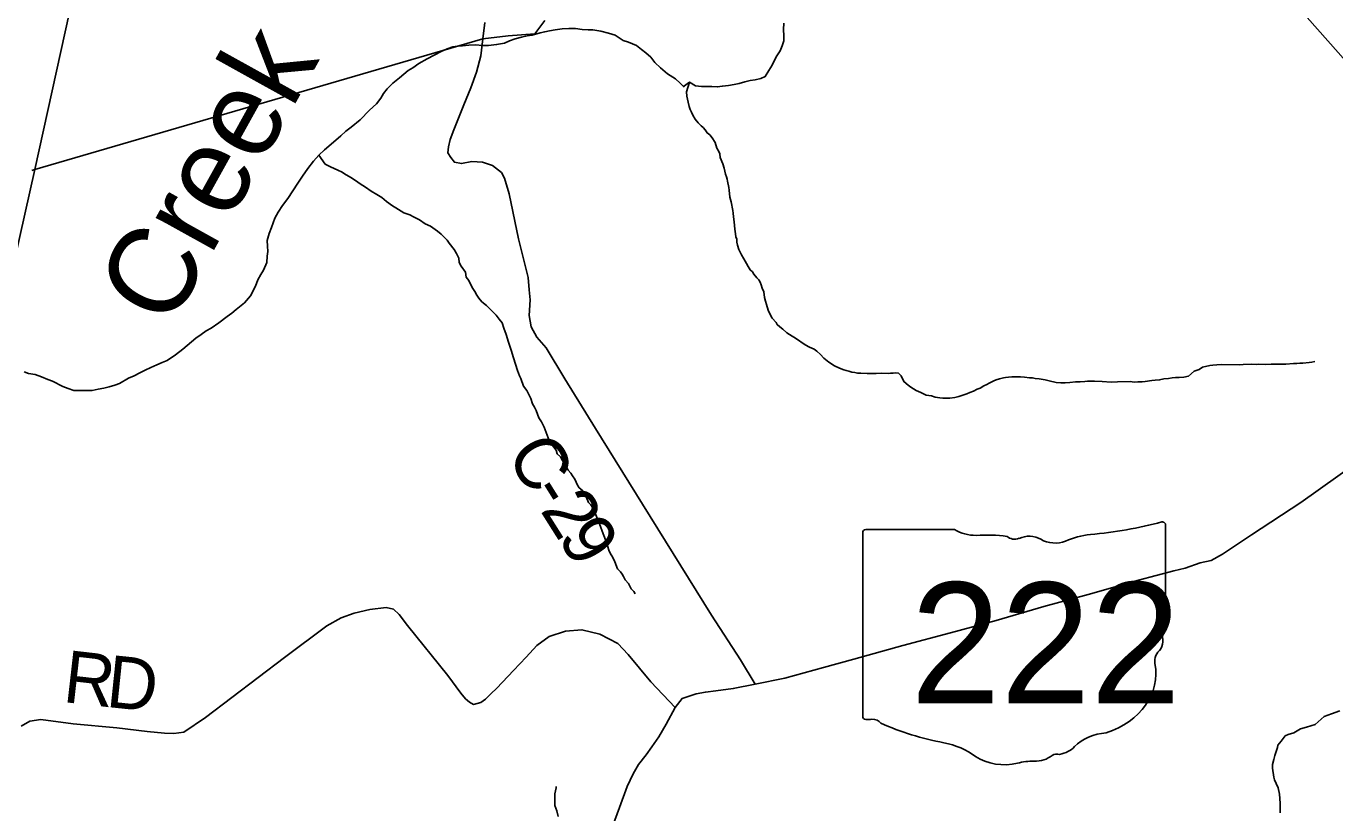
# Model space of a CAD drawing. Extents: x 1310247 to 1664935, y 235267 to 584339.
# Drawn here: x 1499619 to 1507145, y 298459 to 302982 of the extents above; entities that cross this region are included whole.
import ezdxf

# ---------------------------------------------------------------- set-up
doc = ezdxf.new("R2010")
doc.units = 0
for name, color, linetype in [('GM_X_County_Road', 7, 'Continuous'), ('GM_X_County_Road_Text', 7, 'Continuous'), ('GM_X_Minor_River', 7, 'Continuous'), ('GM_X_Minor_River_Text', 7, 'Continuous'), ('GM_X_State_Location', 7, 'Continuous'), ('GM_X_State_Route', 7, 'Continuous'), ('GM_X_State_Shield', 7, 'Continuous'), ('GM_X_Township', 7, 'Continuous'), ('GM_X_Township_Road', 7, 'Continuous'), ('GM_X_Township_Road_Text', 7, 'Continuous'), ('GM_X_Township_ROW', 7, 'Continuous')]:
    doc.layers.add(name, color=color, linetype=linetype)

msp = doc.modelspace()

# ---------------------------------------------------------------- linework, layer by layer
at = {"layer": 'GM_X_County_Road'}
msp.add_lwpolyline([(1503810.8, 299198.2), (1503727.6, 299337.9), (1503560.6, 299594.9), (1503162.8, 300234.4), (1502892.6, 300669.5), (1502716.7, 300955.1), (1502609.1, 301133.2), (1502556.3, 301194.7), (1502523.4, 301254), (1502512.4, 301317.7), (1502516.8, 301407.8), (1502512.4, 301467.1), (1502505.8, 301537.5), (1502450.9, 301759.4), (1502395.9, 302018.7), (1502369.6, 302108.8), (1502352, 302141.8), (1502300.1, 302180.6), (1502243.8, 302199.4), (1502181.8, 302203.7), (1502122.7, 302192.1), (1502082.2, 302199.4), (1502060.6, 302226.8), (1502044.7, 302254.2), (1502047.6, 302288.8), (1502057.7, 302330.7), (1502079.3, 302387), (1502135.6, 302529.8), (1502176, 302627.9), (1502209.2, 302718.8), (1502233.7, 302812.6), (1502245.3, 302909.3), (1502256.9, 303003.1)], dxfattribs=at)
at = {"layer": 'GM_X_Minor_River'}
for points in [[(1503399.3, 302636.4), (1503433.3, 302659.7), (1503469.1, 302639), (1503503.1, 302636.4), (1503561.3, 302635.3), (1503593.4, 302632.7), (1503623.5, 302638.2), (1503657.7, 302641.5), (1503689.9, 302646.9), (1503720.1, 302652.4), (1503752.4, 302661.8), (1503782.6, 302669.3), (1503810.8, 302674.7), (1503843.1, 302682.2), (1503869.4, 302693.7), (1503890.1, 302727.4), (1503908.7, 302759.1), (1503931.7, 302806.7), (1503954.4, 302840.4), (1503967, 302870.2), (1503975.5, 302898.1), (1503976, 302926.1), (1503974.8, 302964.2), (1503975.4, 303000.3)], [(1499893.5, 300887.5), (1499999.4, 300888.1), (1500033.5, 300895.6), (1500065.6, 300901.2), (1500095.7, 300908.8), (1500129.8, 300918.3), (1500155.9, 300928), (1500208.3, 300957.3), (1500240.5, 300970.9), (1500272.8, 300988.5), (1500303, 301004.1), (1500335.2, 301019.6), (1500371.4, 301035.2), (1500401.6, 301048.8), (1500429.7, 301060.4), (1500478.1, 301091.8), (1500520.6, 301125.2), (1500569.1, 301166.6), (1500595.4, 301188.3), (1500625.7, 301209.9), (1500654, 301229.5), (1500682.2, 301245.1), (1500726.6, 301276.6), (1500775.1, 301311.9), (1500801.4, 301331.6), (1500827.7, 301353.2), (1500874.2, 301390.6), (1500908.8, 301432.2), (1500937.5, 301487.8), (1500952, 301523.7), (1500968.4, 301553.5), (1500984.8, 301579.3), (1501003.4, 301623), (1501005.9, 301659), (1501008.3, 301687), (1501006.7, 301717), (1501005.2, 301749.1), (1501015.8, 301791), (1501030.2, 301824.8), (1501049, 301878.6), (1501067.4, 301912.3), (1501094, 301952), (1501124.5, 301991.6), (1501181.7, 302078.9), (1501208.3, 302120.6), (1501238.9, 302164.2), (1501271.5, 302205.8), (1501302, 302241.4), (1501334.4, 302271), (1501399.1, 302326.1), (1501429.5, 302351.8), (1501457.8, 302379.4), (1501488.1, 302401), (1501540.7, 302444.3), (1501593.5, 302499.7), (1501634, 302535.1), (1501658.4, 302568.8), (1501674.8, 302594.6), (1501695.2, 302622.4), (1501727.6, 302654), (1501766, 302685.5), (1501816.6, 302726.8), (1501842.8, 302742.5), (1501877.1, 302768.1), (1501925.5, 302795.5), (1501965.8, 302814.9), (1502006, 302836.4), (1502040.2, 302852), (1502072.4, 302863.5), (1502098.4, 302867.2), (1502128.5, 302868.8), (1502164.5, 302872.3), (1502202.5, 302875.8), (1502242.5, 302871.3), (1502278.4, 302870.8), (1502324.5, 302876.2), (1502370.6, 302885.6), (1502398.8, 302897.2), (1502430.9, 302908.8), (1502467, 302918.3), (1502501.1, 302925.9), (1502529.2, 302931.5), (1502575.4, 302944.9), (1502601.4, 302950.5), (1502629.5, 302956.2), (1502661.6, 302961.8), (1502701.6, 302967.2), (1502739.6, 302968.7), (1502777.6, 302968.2), (1502817.5, 302963.7), (1502851.5, 302961.2), (1502877.5, 302960.9), (1502923.4, 302954.3), (1502967.2, 302941.7), (1503007, 302931.1), (1503052.6, 302900.5), (1503082.4, 302890.1), (1503128.1, 302871.5), (1503157.8, 302849.1), (1503183.5, 302828.7), (1503211.2, 302804.3)], [(1503211.2, 302804.3), (1503234.7, 302774), (1503266.3, 302743.5), (1503307.8, 302709), (1503353.4, 302680.3), (1503381, 302654), (1503404, 302631.9)], [(1503433.3, 302659.7), (1503416.1, 302605.1), (1503417.8, 302579), (1503425.4, 302544.7), (1503431.1, 302520.6), (1503436.9, 302502.5), (1503444.8, 302488.3), (1503452.6, 302470.1), (1503466.4, 302447.9), (1503484.2, 302425.6), (1503500.1, 302409.4), (1503512, 302399.2), (1503523.9, 302387), (1503535.7, 302368.8), (1503551.7, 302356.6), (1503563.5, 302340.4), (1503581.3, 302314.1), (1503590.9, 302281.8), (1503600.8, 302265.7), (1503608.6, 302247.5), (1503610.3, 302227.4), (1503626, 302191.1), (1503633.7, 302164.9), (1503641.3, 302130.7), (1503647.2, 302116.6), (1503651, 302102.5), (1503652.9, 302090.5), (1503660.5, 302054.2), (1503662.3, 302040.2), (1503665.8, 302000), (1503673.5, 301971.8), (1503683, 301921.5), (1503684.8, 301907.5), (1503686.6, 301885.4), (1503690.2, 301857.3), (1503693.7, 301815.1), (1503697.4, 301789), (1503701.2, 301770.8), (1503705.1, 301756.8), (1503706.9, 301740.7), (1503710.7, 301722.6), (1503718.4, 301698.4), (1503732.1, 301668.1), (1503745.9, 301643.9), (1503753.8, 301631.8), (1503761.6, 301617.6), (1503771.5, 301599.5), (1503783.3, 301581.2), (1503795.2, 301569.1), (1503803.1, 301556.9), (1503820.9, 301534.6), (1503832.8, 301524.5), (1503840.7, 301510.3), (1503846.5, 301494.2), (1503852.3, 301476.1), (1503862.1, 301453.9), (1503865.7, 301421.8), (1503871.5, 301401.6), (1503877.3, 301381.5), (1503886.9, 301349.3), (1503892.8, 301335.1), (1503908.5, 301302.9), (1503932.3, 301278.5), (1503938.1, 301266.4), (1503954.1, 301254.1), (1503969.9, 301239.9), (1503993.8, 301219.5), (1504023.7, 301199.1), (1504043.6, 301188.8), (1504099.4, 301150), (1504123.3, 301135.7), (1504151.3, 301125.3), (1504165.2, 301113.1), (1504187.1, 301094.8), (1504206.9, 301072.5), (1504234.7, 301050.1), (1504268.6, 301029.6), (1504296.6, 301015.2), (1504320.6, 301006.9), (1504334.6, 301002.7), (1504350.6, 300998.5), (1504366.6, 300992.3), (1504384.6, 300990), (1504400.7, 300987.8), (1504418.7, 300987.6), (1504454.9, 300985.1), (1504493, 300984.7), (1504507.1, 300984.5), (1504537.2, 300986.1), (1504575.4, 300985.7), (1504589.4, 300987.5), (1504605.5, 300987.3), (1504619.6, 300989.1), (1504635.6, 300986.9), (1504651.5, 300970.7), (1504667.2, 300938.4), (1504691, 300918), (1504706.9, 300905.8), (1504736.8, 300887.4), (1504764.8, 300875), (1504794.7, 300860.6)], [(1501302, 302241.4), (1501338.6, 302189.4), (1501368.5, 302173), (1501410.5, 302154.4), (1501436.4, 302142), (1501450.4, 302133.8), (1501486.3, 302111.3), (1501512.2, 302094.9), (1501540.1, 302076.5), (1501569.9, 302056.1), (1501603.8, 302033.6), (1501635.7, 302015.1), (1501663.6, 301996.7), (1501691.5, 301974.3), (1501725.3, 301949.8), (1501745.2, 301937.5), (1501791.1, 301908.9), (1501825.1, 301898.4), (1501847, 301886.1), (1501881, 301869.6), (1501912.8, 301845.2), (1501944.8, 301832.7), (1501984.6, 301804.2), (1502006.5, 301785.8), (1502040.2, 301751.3), (1502052.1, 301735.1), (1502079.7, 301698.7), (1502093.5, 301674.4), (1502107.2, 301648.2), (1502109, 301624.1), (1502120.7, 301601.8), (1502146.4, 301567.4), (1502150.1, 301539.3), (1502163.9, 301519.1), (1502183.5, 301478.7), (1502199.3, 301456.4), (1502211.1, 301436.2), (1502222.9, 301418), (1502238.8, 301397.8), (1502266.6, 301375.3), (1502294.4, 301346.9), (1502322.2, 301320.5), (1502340, 301298.2), (1502355.8, 301275.9), (1502365.5, 301245.7), (1502379.1, 301209.4), (1502392.6, 301165.1), (1502408.1, 301118.8), (1502421.6, 301074.5), (1502444.8, 301002), (1502456.5, 300971.8), (1502464.4, 300955.6), (1502479.9, 300911.3), (1502497.7, 300887), (1502509.5, 300864.8), (1502521.2, 300840.6), (1502530.9, 300810.4), (1502542.7, 300792.2), (1502552.5, 300772), (1502568.1, 300729.7), (1502581.8, 300707.4), (1502597.6, 300677.1), (1502620.9, 300614.7), (1502632.6, 300588.4), (1502666.2, 300543.9), (1502672, 300523.8), (1502691.9, 300505.5), (1502703.7, 300485.2), (1502719.5, 300463), (1502735.1, 300428.7), (1502751, 300412.5), (1502760.8, 300396.3), (1502774.7, 300378.1), (1502790.3, 300343.8), (1502800.2, 300327.6), (1502816.1, 300313.4), (1502825.9, 300297.2), (1502839.7, 300275), (1502853.4, 300242.7), (1502867.3, 300230.5), (1502875.1, 300214.3), (1502886.9, 300196.1), (1502894.7, 300172), (1502902.5, 300153.8), (1502922, 300105.4), (1502931.7, 300079.2), (1502941.4, 300053), (1502951.2, 300028.8), (1502958.9, 300006.7), (1502970.5, 299968.4), (1502980.3, 299948.2), (1502990.2, 299930.1), (1503003.9, 299901.8), (1503019.4, 299861.5), (1503037.3, 299845.2), (1503047.2, 299831.1), (1503055, 299816.9), (1503062.9, 299798.8), (1503082.7, 299776.5), (1503098.4, 299746.2), (1503114.3, 299732)], [(1504794.7, 300860.6), (1504824.8, 300856.2), (1504846.8, 300849.9), (1504872.9, 300845.6), (1504890.9, 300843.4), (1504931.1, 300842.9), (1504959.3, 300846.5), (1504983.4, 300852.2), (1505027.8, 300867.7), (1505046, 300875.5), (1505066.1, 300883.3), (1505088.4, 300895.1), (1505104.5, 300900.9), (1505126.8, 300914.7), (1505142.9, 300922.5), (1505157.1, 300930.3), (1505183.3, 300942), (1505197.5, 300947.9), (1505215.6, 300953.7), (1505239.8, 300959.4), (1505251.8, 300961.2), (1505267.9, 300963.1), (1505288, 300966.8), (1505338.2, 300966.2), (1505360.3, 300963.9), (1505388.4, 300959.6), (1505406.4, 300959.3), (1505422.5, 300957.1), (1505444.5, 300954.9), (1505478.6, 300948.4), (1505502.6, 300942.1), (1505542.7, 300933.6), (1505568.8, 300931.3), (1505594.9, 300930.9), (1505621, 300932.6), (1505653.2, 300936.2), (1505681.3, 300937.9), (1505707.4, 300939.6), (1505723.5, 300941.4), (1505763.7, 300940.9), (1505807.8, 300938.3), (1505858, 300935.7), (1505894.2, 300937.3), (1505968.5, 300938.3), (1505990.5, 300936.1), (1506012.7, 300937.8), (1506036.8, 300937.5), (1506054.8, 300939.3), (1506093.1, 300944.8), (1506111.2, 300946.6), (1506137.3, 300948.3), (1506161.5, 300954), (1506187.6, 300955.7), (1506209.7, 300959.4), (1506227.8, 300961.2), (1506249.9, 300963), (1506276.1, 300964.6), (1506304.2, 300970.3), (1506336.7, 300998), (1506364.9, 301007.7), (1506383.2, 301021.5), (1506425.5, 301031), (1506443.6, 301032.8), (1506465.7, 301034.5), (1506495.8, 301036.1), (1506596.2, 301034.9), (1506618.3, 301036.6), (1506664.5, 301038.1), (1506692.6, 301037.7), (1506706.7, 301039.6), (1506744.8, 301037.1), (1506779, 301038.7), (1506827.2, 301038.1), (1506863.4, 301039.6), (1506907.6, 301043.1), (1506925.7, 301042.9), (1506943.8, 301044.6), (1506961.8, 301044.4), (1506998, 301048), (1507012.1, 301049.8), (1507030.2, 301053.6)], [(1499607.1, 300995.3), (1499632.9, 300985), (1499670.8, 300978.5), (1499706.6, 300966), (1499744.4, 300951.5), (1499770.3, 300941.1), (1499829.8, 300910.3), (1499861.6, 300897.9), (1499893.5, 300887.5)], [(1503114.3, 299732), (1503122.1, 299717.8)], [(1506830.1, 298458.3), (1506830.8, 298514.5), (1506827.4, 298566.7), (1506819.8, 298602.9), (1506808.1, 298627.1), (1506798.3, 298649.3), (1506794.4, 298663.4), (1506787, 298715.6), (1506787.3, 298735.7), (1506793.7, 298765.7), (1506800, 298787.7), (1506814.6, 298833.7), (1506816.8, 298847.7), (1506837.1, 298871.5), (1506859.6, 298901.3), (1506875.7, 298909.1), (1506910, 298918.8), (1506948.4, 298942.3), (1506982.7, 298952), (1507031.1, 298967.4), (1507083.8, 299012.9), (1507126.2, 299028.4), (1507174.6, 299045.9)], [(1502678, 298437.4), (1502670.5, 298469.6), (1502659, 298501.7), (1502659.9, 298567.8), (1502666.4, 298601.7), (1502666.5, 298609.7)]]:
    msp.add_lwpolyline(points, dxfattribs=at)
at = {"layer": 'GM_X_State_Route'}
msp.add_lwpolyline([(1502978.3, 298344.5), (1503030.7, 298490.2), (1503075.4, 298610.8), (1503109.6, 298683.6), (1503139.9, 298736), (1503183.9, 298792.8), (1503217.3, 298837.6), (1503256.7, 298894.9), (1503299.2, 298968.4), (1503351.3, 299064.5), (1503391, 299115.7), (1503471.8, 299143.1), (1503525.2, 299153.2), (1503585.8, 299160.5), (1503685.4, 299173.5), (1503810.8, 299198.2), (1503981.7, 299232.1), (1504203.7, 299294.7), (1504378.8, 299341.6), (1504661.4, 299420.2), (1504934.4, 299494.6), (1505197.7, 299565), (1505472.1, 299644.9), (1505727.1, 299713.8), (1506015.5, 299796.5), (1506218.8, 299851.1), (1506284.1, 299865.5), (1506370.6, 299895.7), (1506434.1, 299909.2), (1506499.3, 299945.7), (1506562.6, 299988.3), (1506664.8, 300058), (1506948.8, 300243.5), (1507275.4, 300474.9)], dxfattribs=at)
at = {"layer": 'GM_X_State_Shield'}
for p, q in [((1504431, 300069.6), (1504431, 299013)), ((1504957.8, 300087.8), (1504448.2, 300087.8)), ((1506171.2, 299561.3), (1506171.2, 300114)), ((1506171.1, 299561.4), (1506171.2, 299561.3))]:
    msp.add_line(p, q, dxfattribs=at)
for centre, major_axis, start_param, end_param in [((1505551.4, 301528.4), (1845.5, 0), 4.814394, 5.042369), ((1506151.9, 300116.3), (19.4, 0), 6.141152, 7.989035), ((1504451, 300071.9), (20.2, 0), 1.712693, 3.28349), ((1505079.2, 300210.5), (195.5, 0), 4.042523, 4.731795), ((1505144, 299494.6), (702, 0), 1.404758, 1.657858), ((1505386.2, 299955.2), (117.3, 0), 0.950623, 2.079405), ((1505786.7, 299765.1), (371.3, 0), 1.699011, 2.107814), ((1505303.4, 300077.4), (56.4, 0), 3.836095, 5.185415), ((1505537.6, 300122.7), (141.1, 0), 4.081561, 5.145723), ((1506166.8, 299520.7), (30, 0), 1.883978, 3.671073), ((1506150.6, 299559.1), (20.7, 0), 5.05454, 6.418171), ((1505976, 299450.8), (180, 0), 5.934695, 6.695948), ((1506240.6, 299330), (130.9, 0), 2.387724, 3.262537), ((1505654.7, 299259.6), (461.6, 0), 5.101752, 6.440018), ((1504451.2, 299010.7), (20.3, 0), 3.00124, 4.508301), ((1504454.2, 299118.8), (155.2, 0), 4.665946, 4.897461), ((1504486, 298952), (56, 0), 0.519207, 1.627899), ((1505192.6, 299901.4), (1332.7, 0), 4.195997, 4.488961), ((1504795.3, 298538.3), (417, 0), 0.823519, 1.323587), ((1505849.4, 298716.4), (252.8, 0), 1.647645, 2.488434), ((1505246.2, 298946.8), (264.6, 0), 4.026481, 4.996735), ((1505418.5, 298867.7), (141, 0), 4.691044, 5.507374), ((1505546, 298765.3), (39.7, 0), 1.147584, 2.315152), ((1505529.1, 298910.6), (149.1, 0), 4.937069, 5.64225), ((1505399.1, 298581.5), (217.4, 0), 1.495662, 1.94098)]:
    msp.add_ellipse(centre, major_axis=major_axis, ratio=0.8, start_param=start_param, end_param=end_param, dxfattribs=at)
at = {"layer": 'GM_X_Township'}
for points in [[(1498859, 298544.1), (1499669.2, 302157.4), (1500420.1, 305569.3), (1500423.8, 305583), (1501684.1, 311144), (1502172.8, 313259.9), (1502426.4, 314358.1), (1503184.9, 317642.2), (1504578, 323299.9)], [(1504578, 323299.9), (1503184.9, 317642.2), (1502426.4, 314358.1), (1502172.8, 313259.9), (1501684.1, 311144), (1500423.8, 305583), (1500420.1, 305569.3), (1499669.2, 302157.4), (1498859, 298544.1)]]:
    msp.add_lwpolyline(points, dxfattribs=at)
at = {"layer": 'GM_X_Township_Road'}
for points in [[(1508479.7, 301287.5), (1507741, 302178.9), (1506940.9, 303082.2), (1506510.8, 303606.9), (1505968.4, 303769.9)], [(1499590.5, 298957.6), (1499640.6, 298986.2), (1499703.8, 298995.7), (1499888.6, 298970.5), (1500141.4, 298946.8), (1500314.2, 298926.9), (1500414.8, 298916.4), (1500468.5, 298914.5), (1500525.3, 298922.5), (1500650.6, 299006.5), (1501103.8, 299351.6), (1501348.2, 299533.1), (1501429.7, 299580), (1501506.3, 299607.2), (1501596.4, 299628.2), (1501689.1, 299638.7), (1501731, 299630), (1501763.7, 299599.8), (1501811.9, 299535.6), (1502044, 299248.5), (1502119.3, 299147.3), (1502146.5, 299113.9), (1502168.1, 299094.2), (1502191, 299081.8), (1502233.6, 299093.6), (1502260.7, 299112.7), (1502291.4, 299142.1)], [(1502291.4, 299142.1), (1502325.6, 299175.1), (1502421.9, 299277.5), (1502495.3, 299354.7), (1502555.5, 299420.2), (1502627.7, 299473.6), (1502721.5, 299502.5), (1502815.3, 299511.1), (1502917.7, 299486.6), (1503021.6, 299431.8), (1503080.8, 299369.7), (1503212.1, 299211), (1503351.3, 299064.5)]]:
    msp.add_lwpolyline(points, dxfattribs=at)
at = {"layer": 'GM_X_Township_ROW'}
msp.add_lwpolyline([(1499652, 302152.4), (1499669.2, 302157.4), (1502245.3, 302909.3), (1502391, 302926.7), (1502543.7, 302939.2), (1502601.4, 303015.5)], dxfattribs=at)

# ---------------------------------------------------------------- texts
at = {"layer": 'GM_X_County_Road_Text'}
for s, rotation, p in [('C', 300.82303, (1502376.1, 300521.9)), ('-', 302.01199, (1502505.9, 300304.4)), ('2', 302.24031, (1502571.9, 300198.9)), ('9', 302.30667, (1502670.7, 300042.2))]:
    msp.add_text(s, height=300, rotation=rotation, dxfattribs=at).set_placement(p)
at = {"layer": 'GM_X_Minor_River_Text'}
msp.add_text('Creek', height=499.69, rotation=60.96972, dxfattribs=at).set_placement((1500443.2, 301232.8))
at = {"layer": 'GM_X_State_Location'}
for s in ['s', 'r']:
    msp.add_text(s, height=1, dxfattribs=at).set_placement((1505281.6, 299471.1))
msp.add_text('222', height=1, rotation=0.00001, dxfattribs=at).set_placement((1504928.6, 299398.3))
at = {"layer": 'GM_X_State_Shield'}
msp.add_text('222', height=696.1, dxfattribs=at).set_placement((1504705.2, 299087.5))
at = {"layer": 'GM_X_Township_Road_Text'}
for s, rotation, p in [('R', 353.49754, (1499824.3, 299096.8)), ('D', 354.08309, (1500072.4, 299068.5))]:
    msp.add_text(s, height=300, rotation=rotation, dxfattribs=at).set_placement(p)

doc.saveas('drawing.dxf')
